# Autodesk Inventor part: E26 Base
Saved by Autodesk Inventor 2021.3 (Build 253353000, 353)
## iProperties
Created: 2022-08
Part Number: E26 Base
Material: Generic
Document SubType Name: Modeling
Designer: Administrator
Density: 1 g/cm^3
Appearance: Default
Title: E26 Base
Author: Administrator
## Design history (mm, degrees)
feature "E26 Base"
body "Solid1"
